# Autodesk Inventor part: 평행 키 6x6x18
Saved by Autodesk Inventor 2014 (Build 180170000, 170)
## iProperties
Created: 2026-05
Part Number: 평행 키 6x6x18
Material: 강철, 연강
Document SubType Name: Modeling
Designer: dg
Density: 7.86 g/cm^3
Appearance: 강철
Mass: 4.6761 g
Surface Area: 4.37149 cm^2
Volume: 0.594924 cm^3
Author: jhkim
Description: 키 및 해당 키홈
Creation Date: 2026-04-23
Sending System: Autodesk Inventor 2027
Preprocessor: ST-DEVELOPER v20.1
Author: dg
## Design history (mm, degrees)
node "평행 키 6x6x181"
body "Solid1"
node "기준1"
